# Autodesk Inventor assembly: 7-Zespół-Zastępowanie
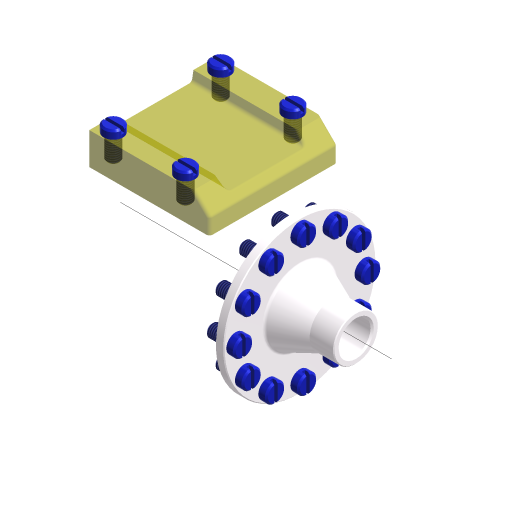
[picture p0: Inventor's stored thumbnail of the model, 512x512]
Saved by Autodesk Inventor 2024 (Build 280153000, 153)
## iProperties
Created: 2023-03
Part Number: 7-Zespół-Zastępowanie
Document SubType Name: Assembly
Designer: Andrzej Jaskulski
Checked By: A.J.
Engr Approved By: Andrzej Jaskulski
Mfg Approved By: Andrzej Jaskulski
Authority: A.J.
Company: ATC
Control State: 0
Master: False
Checked Out: False
Shininess: 20.0
Length Units: 11269
Angle Units: 11279
Time Units: 11290
Mass Units: 11283
Length Display Precision: 3
Angle Display Precision: 2
Compacted: True
Density: 0.0
Volumn: 0.0
Area: 0.0
PropertySet Name: Model Information
Title: A.J.: Kurs R2024-MEP
Author: Andrzej Jaskulski
Revision Number: 1/24
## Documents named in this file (4)
- C:\Users\AndJas\Documents\R2024-MEP\Obszar roboczy\7-Zespół-Zastępowanie.iam
- C:\Users\AndJas\Documents\R2024-MEP\Obszar roboczy\T.ipt
- C:\Users\AndJas\Documents\R2024-MEP\Obszar roboczy\P.ipt
- C:\Users\AndJas\Documents\R2024-MEP\Obszar roboczy\W.ipt
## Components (18 placed, 3 different names)
1. Tuleja — Wstawiające:2, Wstawiające:3, Wstawiające:4, Wstawiające:5, Wstawiające:6, Wstawiające:7, Wstawiające:8, Wstawiające:9, Wstawiające:10, Wstawiające:11, Wstawiające:12, Wstawiające:13
2. Płyta — Wstawiające:1
3. W:17 — Wstawiające:2
4. W:18 — Wstawiające:3
5. W:19 — Wstawiające:4
6. W:20 — Wstawiające:5
7. W:21 — Wstawiające:6
8. W:22 — Wstawiające:7
9. W:23 — Wstawiające:8
10. W:24 — Wstawiające:9
11. W:25 — Wstawiające:10
12. W:26 — Wstawiające:11
13. W:27 — Wstawiające:12
14. W:28 — Wstawiające:13
15. W:1 — Wstawiające:1
16. W:3
17. W:4
18. W:5
## Component patterns: Wkręty w płycie (4 elements)
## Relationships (13: Insert 13)
- Wstawiające:1 [Insert]: Płyta ↔ W:1
- Wstawiające:2 [Insert]: Tuleja ↔ W:17
- Wstawiające:3 [Insert]: Tuleja ↔ W:18
- Wstawiające:4 [Insert]: Tuleja ↔ W:19
- Wstawiające:5 [Insert]: Tuleja ↔ W:20
- Wstawiające:6 [Insert]: Tuleja ↔ W:21
- Wstawiające:7 [Insert]: Tuleja ↔ W:22
- Wstawiające:8 [Insert]: Tuleja ↔ W:23
- Wstawiające:9 [Insert]: Tuleja ↔ W:24
- Wstawiające:10 [Insert]: Tuleja ↔ W:25
- Wstawiające:11 [Insert]: Tuleja ↔ W:26
- Wstawiające:12 [Insert]: Tuleja ↔ W:27
- Wstawiające:13 [Insert]: Tuleja ↔ W:28
